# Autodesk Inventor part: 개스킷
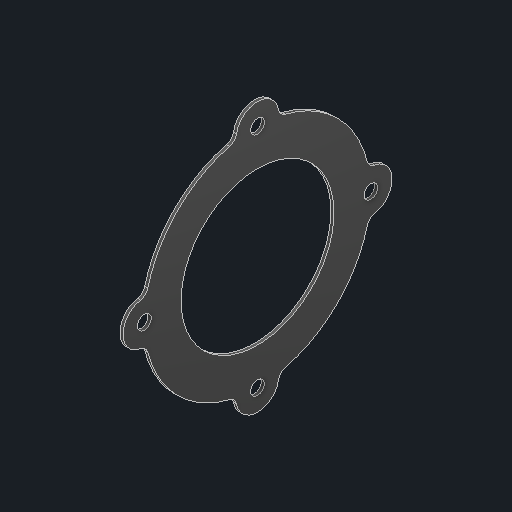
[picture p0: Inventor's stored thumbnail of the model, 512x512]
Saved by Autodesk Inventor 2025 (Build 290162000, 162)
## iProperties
Created: 2025-08
Part Number: 개스킷
Material: 황동, 연질 노란색
Document SubType Name: Modeling
Designer: infra023
Density: 8.47 g/cm^3
Appearance: 기본값
Author: jhkim
Sending System: Autodesk Inventor 2026
Preprocessor: ST-DEVELOPER v20.1
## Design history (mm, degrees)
feature "솔리드2"
node "솔리드1"
